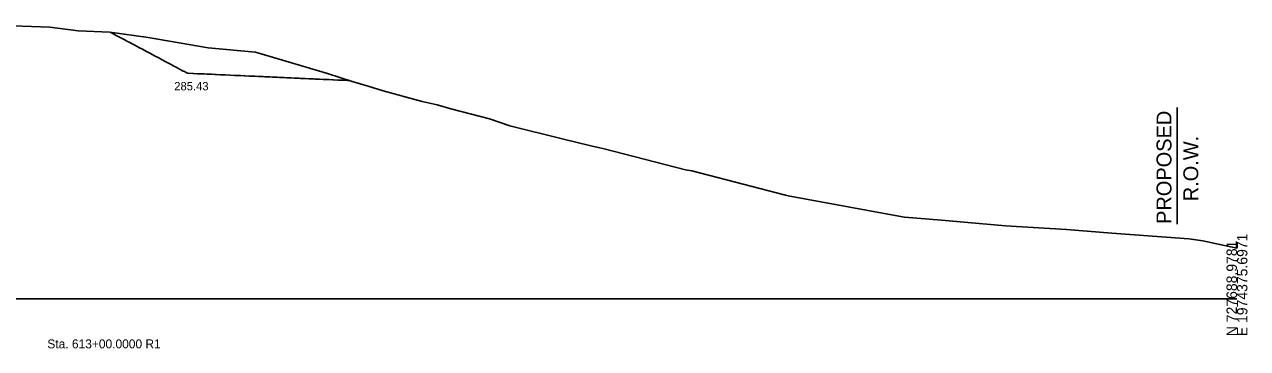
# Model space of a CAD drawing. Extents: x -26 to 1604, y -13 to 9623.
# Drawn here: x 274.6 to 602.8, y 2486.7 to 2573.5 of the extents above; entities that cross this region are included whole.
import ezdxf

# ---------------------------------------------------------------- set-up
doc = ezdxf.new("R2010")
doc.units = 0
for name, color, linetype in [('Draft_XS_Text', 7, 'Continuous'), ('DTM CONTOURS_MAJOR', 7, 'Continuous'), ('DTM_X_GROUND', 7, 'Continuous'), ('XS_CELL', 7, 'Continuous'), ('XS_P_GROUND', 7, 'Continuous'), ('XS_P_ROW', 7, 'Continuous'), ('XS_P_TX_DCH', 7, 'Continuous')]:
    doc.layers.add(name, color=color, linetype=linetype)

msp = doc.modelspace()

# ---------------------------------------------------------------- linework, layer by layer
at = {"layer": 'DTM_X_GROUND'}
msp.add_lwpolyline([(261.66, 2573.47), (281.47, 2572.75), (289.07, 2571.8), (297.57, 2571.4), (307.8, 2570), (323.98, 2567.25), (336.66, 2566.03), (355.99, 2560.32), (362.56, 2558.25), (366.85, 2556.97), (370.92, 2555.74), (381.36, 2552.89), (385.39, 2551.95), (389.06, 2550.89), (399.45, 2548.18), (404.87, 2546.31), (418.92, 2542.9), (426.65, 2540.95), (430.17, 2540.16), (452.03, 2534.59), (453.68, 2534.25), (478.89, 2527.78), (479.6, 2527.63), (509.27, 2522.13), (510.8, 2521.88), (520.7, 2521.04), (537.85, 2519.52), (554.24, 2518.56), (566.44, 2517.63), (587.06, 2516.1), (590.82, 2515.54), (600, 2513.55)], dxfattribs=at)
at = {"layer": 'XS_CELL'}
msp.add_line((100, 2500), (600, 2500), dxfattribs=at)
at = {"layer": 'XS_P_GROUND'}
for points in [[(297.81, 2571.36), (298.38, 2571.06), (298.49, 2570.99), (299.64, 2570.39), (299.98, 2570.2), (300.9, 2569.72), (301.44, 2569.42), (302.15, 2569.05), (302.88, 2568.66), (303.41, 2568.38), (304.29, 2567.91), (304.67, 2567.71), (305.69, 2567.17), (305.93, 2567.04), (307.08, 2566.43), (307.19, 2566.37), (308.45, 2565.7), (308.45, 2565.7), (308.48, 2565.68), (309.57, 2565.1), (309.71, 2565.03), (310.69, 2564.51), (310.97, 2564.36), (311.81, 2563.91), (312.23, 2563.69), (312.92, 2563.32), (313.49, 2563.02), (314.04, 2562.73), (314.75, 2562.35), (315.16, 2562.13), (316.01, 2561.68), (316.27, 2561.54), (317.27, 2561.01), (317.39, 2560.94), (318.35, 2560.43)], [(361.92, 2558.45), (361.35, 2558.48), (361.33, 2558.48), (360.09, 2558.54), (360.03, 2558.54), (358.83, 2558.59), (358.73, 2558.6), (357.57, 2558.65), (357.43, 2558.66), (356.31, 2558.71), (356.12, 2558.72), (355.05, 2558.76), (354.82, 2558.78), (353.79, 2558.82), (353.52, 2558.83), (352.53, 2558.88), (352.21, 2558.89), (351.27, 2558.94), (350.91, 2558.95), (350.01, 2558.99), (349.6, 2559.01), (348.75, 2559.05), (348.3, 2559.07), (347.49, 2559.11), (346.99, 2559.13), (346.23, 2559.17), (345.68, 2559.19), (344.98, 2559.22), (344.37, 2559.25), (343.72, 2559.28), (343.07, 2559.31), (342.46, 2559.34), (341.76, 2559.37), (341.2, 2559.39), (340.45, 2559.43), (339.94, 2559.45), (339.14, 2559.49), (338.68, 2559.51), (337.82, 2559.55), (337.42, 2559.57), (336.51, 2559.61), (336.16, 2559.62), (335.2, 2559.67), (334.9, 2559.68), (333.88, 2559.73), (333.64, 2559.74), (332.57, 2559.79), (332.38, 2559.79), (331.25, 2559.85), (331.12, 2559.85), (331, 2559.86), (329.86, 2559.91), (329.79, 2559.91), (328.6, 2559.97), (328.59, 2559.97), (328.22, 2559.98), (327.34, 2560.02), (327.21, 2560.03), (326.08, 2560.08), (325.77, 2560.1), (324.82, 2560.14), (324.33, 2560.16), (323.56, 2560.2), (322.88, 2560.23), (322.31, 2560.25), (321.44, 2560.29), (321.05, 2560.31), (320, 2560.36), (319.79, 2560.37), (318.55, 2560.42), (318.53, 2560.42), (318.35, 2560.43)]]:
    msp.add_lwpolyline(points, dxfattribs=at)
at = {"layer": 'XS_P_ROW'}
msp.add_line((584, 2551.27), (584, 2520), dxfattribs=at)

# ---------------------------------------------------------------- texts
at = {"layer": 'Draft_XS_Text'}
msp.add_text('Sta. 613+00.0000 R1', height=2.4, dxfattribs=at).set_placement((280.78, 2486.75))
at = {"layer": 'DTM CONTOURS_MAJOR'}
for p in [(308.44, 2565.62), (318.31, 2560.37), (318.31, 2560.37), (328.18, 2559.92), (361.88, 2558.39)]:
    msp.add_text('X', height=0.12, dxfattribs=at).set_placement(p)
at = {"layer": 'XS_CELL'}
for s, p in [('E 1974375.6971', (602.8, 2490)), ('N 727688.9781', (600, 2490))]:
    msp.add_text(s, height=2.8, rotation=90, dxfattribs=at).set_placement(p)
at = {"layer": 'XS_P_ROW'}
for s, p in [('PROPOSED', (582.42, 2520.07)), ('R.O.W.', (589.62, 2526.14))]:
    msp.add_text(s, height=4, rotation=90, dxfattribs=at).set_placement(p)
at = {"layer": 'XS_P_TX_DCH'}
msp.add_text('285.43', height=2.25, dxfattribs=at).set_placement((314.84, 2555.84))

doc.saveas('drawing.dxf')
